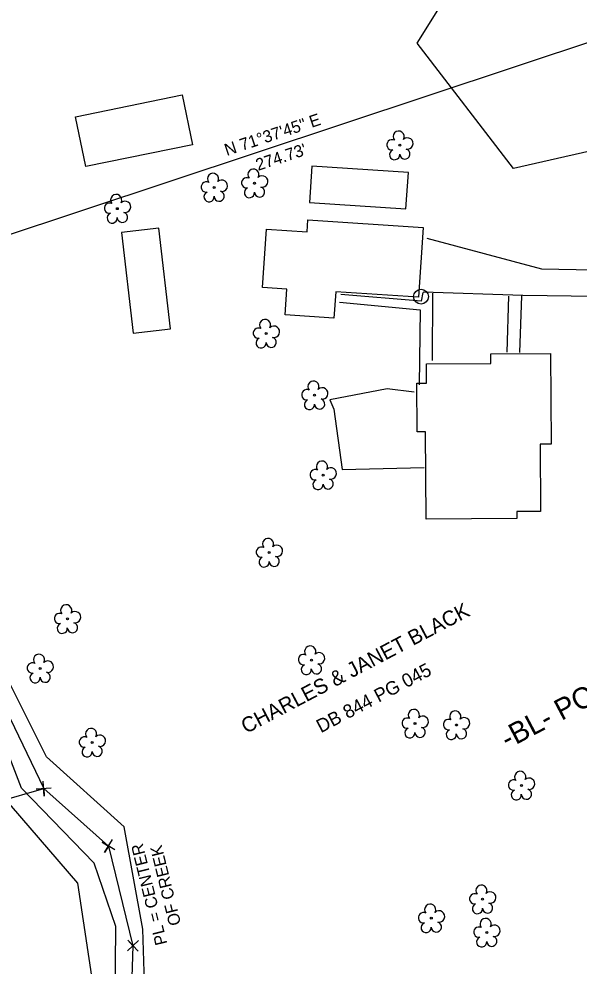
# Model space of a CAD drawing. Extents: x 1380524 to 1382335, y 594765 to 596944.
# Drawn here: x 1381565.9 to 1381752.4, y 595723.8 to 596039.1 of the extents above; entities that cross this region are included whole.
import ezdxf

# ---------------------------------------------------------------- set-up
doc = ezdxf.new("R2010")
doc.units = 0
for name, color, linetype in [('DTM Contours Major Text', 7, 'Continuous'), ('Exist Hydro Jurisdictional Stream or Body of Water', 7, 'Continuous'), ('Exist Other Culture Fence Line Text', 7, 'Continuous'), ('Exist Right of Way Line', 7, 'Continuous'), ('Exist Structure Major Bridge WW', 7, 'Continuous'), ('Exist Structure Minor Pipes CMP 18 Inch', 7, 'Continuous'), ('Exist Utilities Power Tower Text', 7, 'Continuous'), ('Prop Drainage Ditch Base Lines', 7, 'Continuous'), ('Prop Drainage Structure Plot Symbol 50 Scale CELL', 7, 'Continuous'), ('Prop Earthen Structure Cut Ditch Special Detail Label', 7, 'Continuous'), ('Prop Earthen Structure Ditch Flow Line', 7, 'Continuous'), ('Prop Erosion Rip Rap At Embankment Detail CELL', 7, 'Continuous'), ('Scratch_Level_6', 7, 'Continuous')]:
    doc.layers.add(name, color=color, linetype=linetype)

# ---------------------------------------------------------------- blocks, each defined once
blk = doc.blocks.new('EXIST UTILITIES OTHER POLE')
at = {"layer": 'DTM Contours Major Text'}
blk.add_circle((0, 0), 0.0493, dxfattribs=at)
blk = doc.blocks.new('EXIST VEGETATION TREE')
at = {"layer": 'Prop Erosion Rip Rap At Embankment Detail CELL'}
blk.add_line((0, 0), (0, 0), dxfattribs=at)
blk.add_circle((0, 0), 0.00652, dxfattribs=at)
for centre, radius, start, end in [((-0.0077, 0.0575), 0.0371, 330.16508, 219.71335), ((-0.0521, 0.0031), 0.0345, 62.66361, 279.3457), ((0.051, 0.0118), 0.038, 257.1011, 134.19993), ((-0.0341, -0.0624), 0.0338, 111.56708, 6.23104), ((0.0335, -0.058), 0.034, 181.28216, 74.55999)]:
    blk.add_arc(centre, radius, start, end, dxfattribs=at)

msp = doc.modelspace()

# ---------------------------------------------------------------- linework, layer by layer
at = {"layer": 'Exist Hydro Jurisdictional Stream or Body of Water'}
for points in [[(1381577.96, 595605.83), (1381583.71, 595643.65), (1381597.79, 595698.93), (1381598.19, 595737), (1381590.93, 595758.1), (1381566.71, 595783.08), (1381549.63, 595827.2), (1381521.68, 595855.93), (1381508.31, 595880.93), (1381498.43, 595922.32), (1381488.98, 595942.12), (1381494.82, 595973.98), (1381493.85, 596010.61), (1381489.16, 596026.09), (1381477.05, 596042.66), (1381466.32, 596071.54), (1381460.24, 596113.74), (1381470.05, 596141.17)], [(1381591.28, 595608.86), (1381593.5, 595640.64), (1381608.3, 595697.05), (1381607.14, 595736.14), (1381600.89, 595770.21), (1381575.06, 595793.44), (1381555.94, 595831.43), (1381528.67, 595862.58), (1381515.5, 595885.72), (1381506.46, 595926.94), (1381508.98, 595973.98), (1381507.81, 596016.05), (1381489.64, 596056.36), (1381476.02, 596075.92), (1381476.25, 596113.98), (1381483.98, 596135.61)]]:
    msp.add_lwpolyline(points, dxfattribs=at)
at = {"layer": 'Exist Structure Major Bridge WW'}
for p, q in [((1381574.12, 595782.88), (1381574.12, 595782.88)), ((1381595.69, 595763.76), (1381595.69, 595763.76)), ((1381603.82, 595730.58), (1381603.82, 595730.58))]:
    msp.add_line(p, q, dxfattribs=at)
for points in [[(1381576.62, 595783.03), (1381571.63, 595782.73), (1381574.12, 595782.88), (1381574.27, 595780.39), (1381573.97, 595785.38)], [(1381597.83, 595762.46), (1381593.55, 595765.06), (1381595.69, 595763.76), (1381594.39, 595761.62), (1381596.98, 595765.9)], [(1381605.52, 595728.75), (1381602.12, 595732.41), (1381603.82, 595730.58), (1381601.99, 595728.87), (1381605.65, 595732.28)]]:
    msp.add_lwpolyline(points, dxfattribs=at)
at = {"layer": 'Exist Utilities Power Tower Text'}
for p, q in [((1381499.76, 595946.4), (1381765.24, 596034.56)), ((1381551.49, 595829.97), (1381574.12, 595782.88)), ((1381224.21, 595682.33), (1381574.12, 595782.88)), ((1381574.12, 595782.88), (1381595.69, 595763.76)), ((1381595.69, 595763.76), (1381603.82, 595730.58)), ((1381603.82, 595730.58), (1381602.63, 595697))]:
    msp.add_line(p, q, dxfattribs=at)
at = {"layer": 'Prop Drainage Ditch Base Lines'}
for points in [[(1381584.76, 596006.52), (1381620.26, 596013.77), (1381623.64, 595997.22), (1381588.14, 595989.97)], [(1381662.58, 595977.93), (1381694.73, 595975.82), (1381695.53, 595987.99), (1381663.38, 595990.1)], [(1381662.09, 595972.22), (1381700.47, 595969.62), (1381698.91, 595946.41), (1381671.36, 595948.27), (1381670.76, 595939.45), (1381654.52, 595940.55), (1381655.09, 595949.09), (1381647.01, 595949.63), (1381648.33, 595969.14), (1381661.82, 595968.23)], [(1381600.06, 595967.96), (1381603.93, 595934.45), (1381616.36, 595935.89), (1381612.48, 595969.4)], [(1381701.44, 595872.56), (1381701.27, 595901.63), (1381698.47, 595901.61), (1381698.37, 595917.8), (1381701.62, 595917.82), (1381701.58, 595924.26), (1381722.99, 595924.39), (1381722.97, 595927.6), (1381742.9, 595927.72), (1381743.08, 595897.53), (1381739.42, 595897.51), (1381739.55, 595875.13), (1381731.62, 595875.08), (1381731.64, 595872.74)]]:
    msp.add_lwpolyline(points, close=True, dxfattribs=at)
at = {"layer": 'Prop Drainage Structure Plot Symbol 50 Scale CELL'}
for p, q in [((1381703.58, 595925.42), (1381703.64, 595947.74)), ((1381728.87, 595946.82), (1381728.33, 595928.11)), ((1381733.15, 595946.89), (1381732.48, 595928.07))]:
    msp.add_line(p, q, dxfattribs=at)
for points in [[(1381700.31, 595947.97), (1381699.81, 595945.1), (1381673.03, 595947.3)], [(1381672.57, 595944.77), (1381699.48, 595942.3), (1381699.15, 595917.33)], [(1381697.5, 595914.88), (1381688.47, 595915.99), (1381669.37, 595912.24), (1381670.71, 595909.22), (1381673.53, 595889.08), (1381700.8, 595889.8)]]:
    msp.add_lwpolyline(points, dxfattribs=at)
at = {"layer": 'Prop Earthen Structure Cut Ditch Special Detail Label'}
for points in [[(1381465.14, 596147.24), (1381454.4, 596115.71), (1381460.79, 596073.39), (1381474.76, 596036.69), (1381485.85, 596011.46), (1381489.74, 595978.87), (1381483.02, 595940.04), (1381494.86, 595911.17), (1381503.32, 595869.73), (1381526.27, 595838.58), (1381548.46, 595817.76), (1381559.9, 595781.05), (1381585.35, 595751.36), (1381590.99, 595713.84), (1381582.97, 595667.85), (1381576.78, 595627.99), (1381575.28, 595604.8), (1381583.28, 595579.61), (1381595.01, 595565.4), (1381637.18, 595526.27), (1381634, 595523.66)], [(1381763.26, 596056.35), (1381789.24, 595986.58), (1381768.13, 595997.86), (1381730.48, 595989.33), (1381698.5, 596031.05), (1381723.1, 596070.54)]]:
    msp.add_lwpolyline(points, dxfattribs=at)
at = {"layer": 'Prop Earthen Structure Ditch Flow Line'}
for points in [[(1381701.67, 595966.11), (1381739.83, 595955.93), (1381774.45, 595955.2), (1381793.07, 595955.39), (1381802.07, 595960.27), (1381805.56, 595965.08)], [(1381815.33, 595943.41), (1381802.45, 595945.14), (1381773.95, 595946.45), (1381733.61, 595947.02), (1381700.47, 595948.15)]]:
    msp.add_lwpolyline(points, dxfattribs=at)

# ---------------------------------------------------------------- block references
at = {"layer": 'DTM Contours Major Text', "xscale": 50, "yscale": 50}
msp.add_blockref('EXIST UTILITIES OTHER POLE', (1381699.74, 595946.63), dxfattribs=at)
at = {"layer": 'Prop Erosion Rip Rap At Embankment Detail CELL', "xscale": 50, "yscale": 50}
for p in [(1381692.67, 595997.01), (1381644.32, 595984.36), (1381630.86, 595982.97), (1381598.64, 595975.92), (1381648.21, 595934.33), (1381664.32, 595913.83), (1381667.14, 595887.19), (1381649.22, 595861.43), (1381582.01, 595839.35), (1381663.24, 595825.66), (1381572.95, 595822.88), (1381697.74, 595804.52), (1381711.52, 595804.05), (1381590.27, 595798.22), (1381733.15, 595783.92), (1381720.24, 595746.04), (1381703.17, 595739.74), (1381721.63, 595734.96)]:
    msp.add_blockref('EXIST VEGETATION TREE', p, dxfattribs=at)

# ---------------------------------------------------------------- texts
at = {"layer": 'Exist Other Culture Fence Line Text'}
for s, rotation, p in [('N 71%%D37\'45" E', 18.3708, (1381635.09, 595993.44)), ("274.73'", 18.3708, (1381645.48, 595988.47)), ('PL = CENTER', 103.7699, (1381615.3, 595731.3)), ('OF CREEK', 103.7699, (1381619.88, 595737.83))]:
    msp.add_text(s, height=4, rotation=rotation, dxfattribs=at).set_placement(p)
at = {"layer": 'Exist Right of Way Line'}
msp.add_text('CHARLES & JANET BLACK', height=5, rotation=27.8065, dxfattribs=at).set_placement((1381641.51, 595801.06))
at = {"layer": 'Exist Structure Minor Pipes CMP 18 Inch'}
msp.add_text('DB 844 PG 045', height=4.5, rotation=27.8065, dxfattribs=at).set_placement((1381666.4, 595801.3))
at = {"layer": 'Scratch_Level_6'}
msp.add_text('-BL- POT 13+58.76 ', height=7, rotation=27.7977, dxfattribs=at).set_placement((1381728.54, 595795.94))

doc.saveas('drawing.dxf')
